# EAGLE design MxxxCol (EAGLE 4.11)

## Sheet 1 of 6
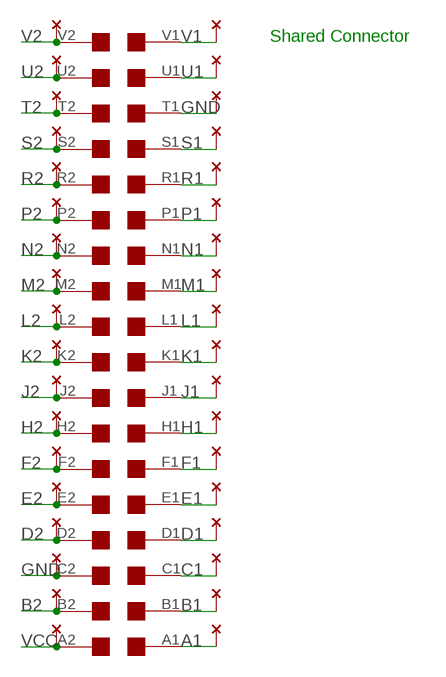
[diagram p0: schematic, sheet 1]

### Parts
U$1  EDGE-2  [EDGE-CON2]
U$4  THRU-HOLE2  [THRU-HOLEB]

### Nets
A1: U$1.A1 U$4.A2 ; also sheet 2,3,4,5,6
B1: U$1.B1 U$4.B2 ; also sheet 2,3,4,5,6
B2: U$1.B2 U$4.B1
C1: U$1.C1 U$4.C2 ; also sheet 2,3,4,5,6
D1: U$1.D1 U$4.D2 ; also sheet 2,3,4,5,6
D2: U$1.D2 U$4.D1 ; also sheet 2,3,4,5,6
E1: U$1.E1 U$4.E2 ; also sheet 2,3,4,5
E2: U$1.E2 U$4.E1 ; also sheet 2,3,4,5,6
F1: U$1.F1 U$4.F2 ; also sheet 2,3,4,5,6
F2: U$1.F2 U$4.F1 ; also sheet 2,3,4,5,6
GND [Power]: U$1.C2 U$1.T1 U$4.C1 U$4.T2 ; also sheet 2,3,4,5,6
H1: U$1.H1 U$4.H2 ; also sheet 2,3,4,5,6
H2: U$1.H2 U$4.H1 ; also sheet 2,3,4,5,6
J1: U$1.J1 U$4.J2 ; also sheet 2,3,4,5,6
J2: U$1.J2 U$4.J1 ; also sheet 2,3,4,5,6
K1: U$1.K1 U$4.K2 ; also sheet 2,3,4,5,6
K2: U$1.K2 U$4.K1 ; also sheet 2,3,4,5,6
L1: U$1.L1 U$4.L2 ; also sheet 2,3,4,5
L2: U$1.L2 U$4.L1 ; also sheet 2,3,4,5,6
M1: U$1.M1 U$4.M2 ; also sheet 2,3,4,5,6
M2: U$1.M2 U$4.M1 ; also sheet 2,3,4,5,6
N1: U$1.N1 U$4.N2 ; also sheet 2,3,4,5,6
N2: U$1.N2 U$4.N1 ; also sheet 2,3,4,5,6
P1: U$1.P1 U$4.P2 ; also sheet 2,3,4,5,6
P2: U$1.P2 U$4.P1 ; also sheet 2,3,4,5,6
R1: U$1.R1 U$4.R2 ; also sheet 2,3,4,5,6
R2: U$1.R2 U$4.R1 ; also sheet 2,3,4,5,6
S1: U$1.S1 U$4.S2 ; also sheet 2,3,4,5
S2: U$1.S2 U$4.S1 ; also sheet 2,3,4,5,6
T2: U$1.T2 U$4.T1 ; also sheet 2,3,4,5,6
U1: U$1.U1 U$4.U2 ; also sheet 2,3,4
U2: U$1.U2 U$4.U1 ; also sheet 2,3,4,5,6
V1: U$1.V1 U$4.V2 ; also sheet 2,3,4
V2: U$1.V2 U$4.V1 ; also sheet 2,3,4,5,6
VCC [Power]: U$1.A2 U$4.A1 ; also sheet 2,3,4,5,6

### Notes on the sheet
- Shared Connector

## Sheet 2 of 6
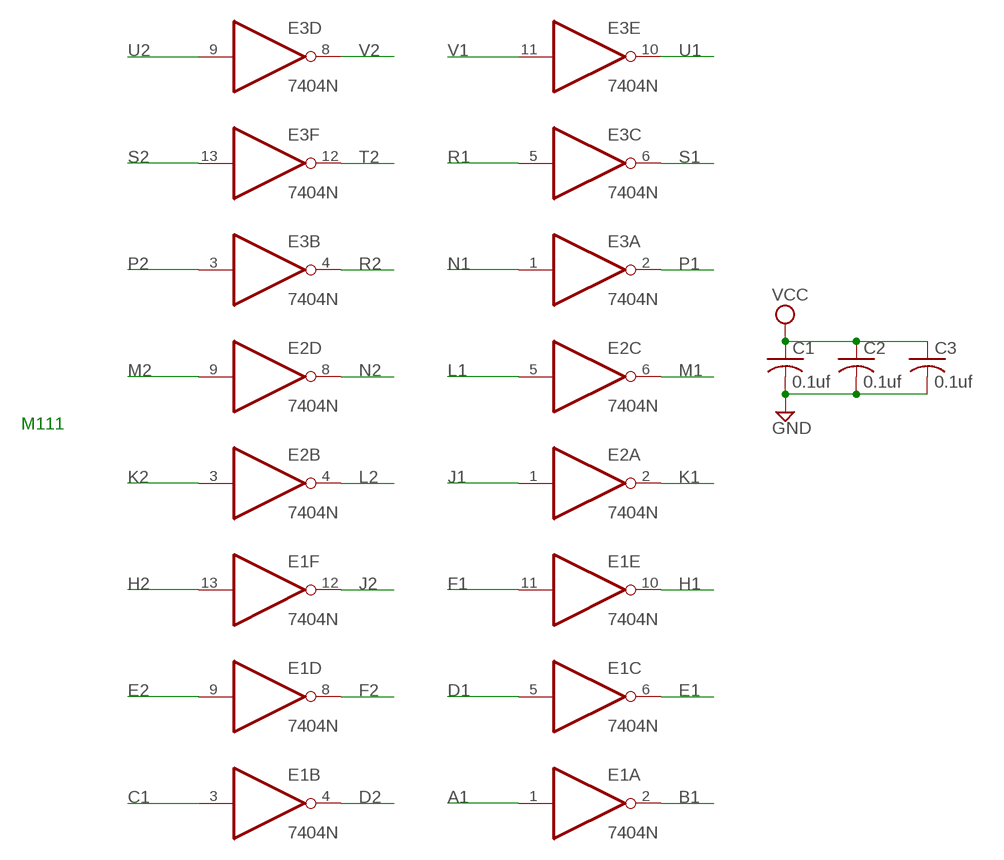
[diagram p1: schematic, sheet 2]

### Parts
C1  0.1uf  C-US050-025X075  [C050-025X075]
C2  0.1uf  C-US050-025X075  [C050-025X075]
C3  0.1uf  C-US050-025X075  [C050-025X075]
E1  7404N  [DIL14]
E2  7404N  [DIL14]
E3  7404N  [DIL14]

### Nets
A1: E1.1(A:I) ; also sheet 1,3,4,5,6
B1: E1.2(A:O) ; also sheet 1,3,4,5,6
C1: E1.3(B:I) ; also sheet 1,3,4,5,6
D1: E1.5(C:I) ; also sheet 1,3,4,5,6
D2: E1.4(B:O) ; also sheet 1,3,4,5,6
E1: E1.6(C:O) ; also sheet 1,3,4,5
E2: E1.9(D:I) ; also sheet 1,3,4,5,6
F1: E1.11(E:I) ; also sheet 1,3,4,5,6
F2: E1.8(D:O) ; also sheet 1,3,4,5,6
GND [Power]: C1.2 C2.2 C3.2 ; also sheet 1,3,4,5,6
H1: E1.10(E:O) ; also sheet 1,3,4,5,6
H2: E1.13(F:I) ; also sheet 1,3,4,5,6
J1: E2.1(A:I) ; also sheet 1,3,4,5,6
J2: E1.12(F:O) ; also sheet 1,3,4,5,6
K1: E2.2(A:O) ; also sheet 1,3,4,5,6
K2: E2.3(B:I) ; also sheet 1,3,4,5,6
L1: E2.5(C:I) ; also sheet 1,3,4,5
L2: E2.4(B:O) ; also sheet 1,3,4,5,6
M1: E2.6(C:O) ; also sheet 1,3,4,5,6
M2: E2.9(D:I) ; also sheet 1,3,4,5,6
N1: E3.1(A:I) ; also sheet 1,3,4,5,6
N2: E2.8(D:O) ; also sheet 1,3,4,5,6
P1: E3.2(A:O) ; also sheet 1,3,4,5,6
P2: E3.3(B:I) ; also sheet 1,3,4,5,6
R1: E3.5(C:I) ; also sheet 1,3,4,5,6
R2: E3.4(B:O) ; also sheet 1,3,4,5,6
S1: E3.6(C:O) ; also sheet 1,3,4,5
S2: E3.13(F:I) ; also sheet 1,3,4,5,6
T2: E3.12(F:O) ; also sheet 1,3,4,5,6
U1: E3.10(E:O) ; also sheet 1,3,4
U2: E3.9(D:I) ; also sheet 1,3,4,5,6
V1: E3.11(E:I) ; also sheet 1,3,4
V2: E3.8(D:O) ; also sheet 1,3,4,5,6
VCC [Power]: C1.1 C2.1 C3.1 ; also sheet 1,3,4,5,6
Unconnected: E2.10(E:O) E2.11(E:I) E2.12(F:O) E2.13(F:I)

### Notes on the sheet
- M111

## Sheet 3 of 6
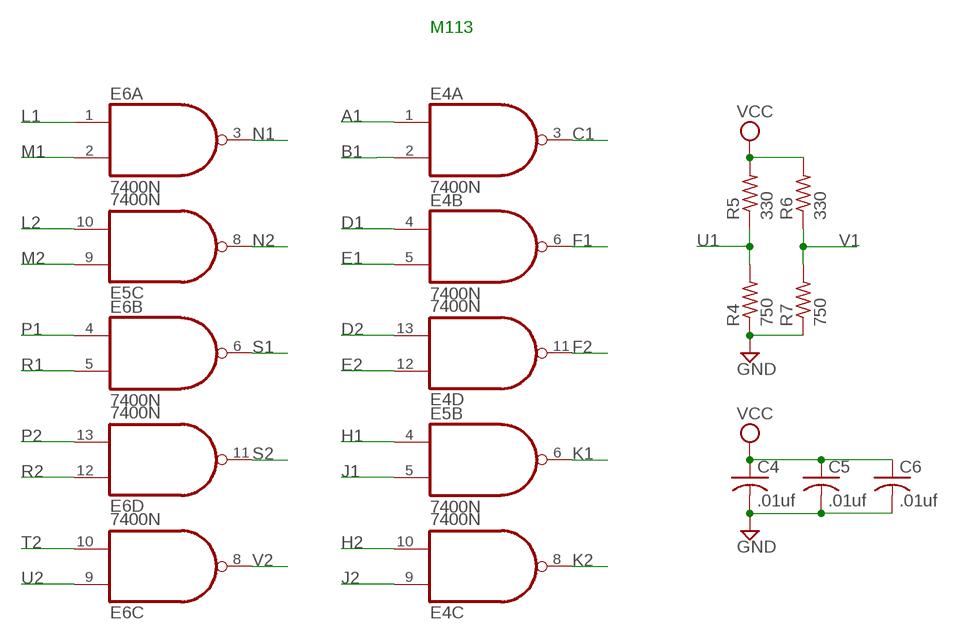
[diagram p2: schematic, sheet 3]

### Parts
C4  .01uf  C-US050-025X075  [C050-025X075]
C5  .01uf  C-US050-025X075  [C050-025X075]
C6  .01uf  C-US050-025X075  [C050-025X075]
E4  7400N  [DIL14]
E5  7400N  [DIL14]
E6  7400N  [DIL14]
R4  750  R-US_0207/10  [0207/10]
R5  330  R-US_0207/10  [0207/10]
R6  330  R-US_0207/10  [0207/10]
R7  750  R-US_0207/10  [0207/10]

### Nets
A1: E4.1(A:I0) ; also sheet 1,2,4,5,6
B1: E4.2(A:I1) ; also sheet 1,2,4,5,6
C1: E4.3(A:O) ; also sheet 1,2,4,5,6
D1: E4.4(B:I0) ; also sheet 1,2,4,5,6
D2: E4.13(D:I1) ; also sheet 1,2,4,5,6
E1: E4.5(B:I1) ; also sheet 1,2,4,5
E2: E4.12(D:I0) ; also sheet 1,2,4,5,6
F1: E4.6(B:O) ; also sheet 1,2,4,5,6
F2: E4.11(D:O) ; also sheet 1,2,4,5,6
GND [Power]: C4.2 C5.2 C6.2 R4.1 R7.1 ; also sheet 1,2,4,5,6
H1: E5.4(B:I0) ; also sheet 1,2,4,5,6
H2: E4.10(C:I1) ; also sheet 1,2,4,5,6
J1: E5.5(B:I1) ; also sheet 1,2,4,5,6
J2: E4.9(C:I0) ; also sheet 1,2,4,5,6
K1: E5.6(B:O) ; also sheet 1,2,4,5,6
K2: E4.8(C:O) ; also sheet 1,2,4,5,6
L1: E6.1(A:I0) ; also sheet 1,2,4,5
L2: E5.10(C:I1) ; also sheet 1,2,4,5,6
M1: E6.2(A:I1) ; also sheet 1,2,4,5,6
M2: E5.9(C:I0) ; also sheet 1,2,4,5,6
N1: E6.3(A:O) ; also sheet 1,2,4,5,6
N2: E5.8(C:O) ; also sheet 1,2,4,5,6
P1: E6.4(B:I0) ; also sheet 1,2,4,5,6
P2: E6.13(D:I1) ; also sheet 1,2,4,5,6
R1: E6.5(B:I1) ; also sheet 1,2,4,5,6
R2: E6.12(D:I0) ; also sheet 1,2,4,5,6
S1: E6.6(B:O) ; also sheet 1,2,4,5
S2: E6.11(D:O) ; also sheet 1,2,4,5,6
T2: E6.10(C:I1) ; also sheet 1,2,4,5,6
U1: R4.2 R5.1 ; also sheet 1,2,4
U2: E6.9(C:I0) ; also sheet 1,2,4,5,6
V1: R6.1 R7.2 ; also sheet 1,2,4
V2: E6.8(C:O) ; also sheet 1,2,4,5,6
VCC [Power]: C4.1 C5.1 C6.1 R5.2 R6.2 ; also sheet 1,2,4,5,6
Unconnected: E5.1(A:I0) E5.2(A:I1) E5.3(A:O) E5.11(D:O) E5.12(D:I0) E5.13(D:I1)

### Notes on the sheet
- M113

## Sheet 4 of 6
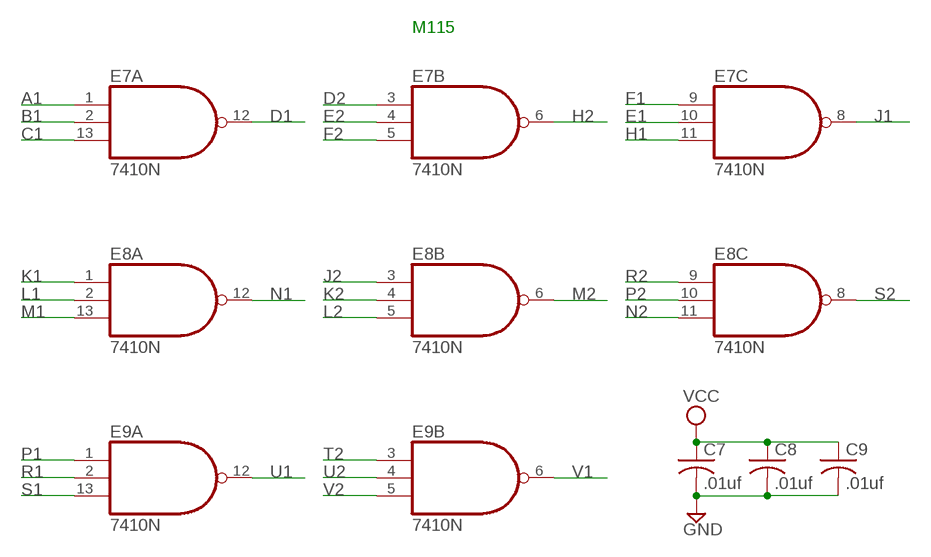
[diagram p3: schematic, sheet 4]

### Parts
C7  .01uf  C-US050-025X075  [C050-025X075]
C8  .01uf  C-US050-025X075  [C050-025X075]
C9  .01uf  C-US050-025X075  [C050-025X075]
E7  7410N  [DIL14]
E8  7410N  [DIL14]
E9  7410N  [DIL14]

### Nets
A1: E7.1(A:I0) ; also sheet 1,2,3,5,6
B1: E7.2(A:I1) ; also sheet 1,2,3,5,6
C1: E7.13(A:I2) ; also sheet 1,2,3,5,6
D1: E7.12(A:O) ; also sheet 1,2,3,5,6
D2: E7.3(B:I0) ; also sheet 1,2,3,5,6
E1: E7.10(C:I1) ; also sheet 1,2,3,5
E2: E7.4(B:I1) ; also sheet 1,2,3,5,6
F1: E7.9(C:I0) ; also sheet 1,2,3,5,6
F2: E7.5(B:I2) ; also sheet 1,2,3,5,6
GND [Power]: C7.2 C8.2 C9.2 ; also sheet 1,2,3,5,6
H1: E7.11(C:I2) ; also sheet 1,2,3,5,6
H2: E7.6(B:O) ; also sheet 1,2,3,5,6
J1: E7.8(C:O) ; also sheet 1,2,3,5,6
J2: E8.3(B:I0) ; also sheet 1,2,3,5,6
K1: E8.1(A:I0) ; also sheet 1,2,3,5,6
K2: E8.4(B:I1) ; also sheet 1,2,3,5,6
L1: E8.2(A:I1) ; also sheet 1,2,3,5
L2: E8.5(B:I2) ; also sheet 1,2,3,5,6
M1: E8.13(A:I2) ; also sheet 1,2,3,5,6
M2: E8.6(B:O) ; also sheet 1,2,3,5,6
N1: E8.12(A:O) ; also sheet 1,2,3,5,6
N2: E8.11(C:I2) ; also sheet 1,2,3,5,6
P1: E9.1(A:I0) ; also sheet 1,2,3,5,6
P2: E8.10(C:I1) ; also sheet 1,2,3,5,6
R1: E9.2(A:I1) ; also sheet 1,2,3,5,6
R2: E8.9(C:I0) ; also sheet 1,2,3,5,6
S1: E9.13(A:I2) ; also sheet 1,2,3,5
S2: E8.8(C:O) ; also sheet 1,2,3,5,6
T2: E9.3(B:I0) ; also sheet 1,2,3,5,6
U1: E9.12(A:O) ; also sheet 1,2,3
U2: E9.4(B:I1) ; also sheet 1,2,3,5,6
V1: E9.6(B:O) ; also sheet 1,2,3
V2: E9.5(B:I2) ; also sheet 1,2,3,5,6
VCC [Power]: C7.1 C8.1 C9.1 ; also sheet 1,2,3,5,6
Unconnected: E9.8(C:O) E9.9(C:I0) E9.10(C:I1) E9.11(C:I2)

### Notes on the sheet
- M115

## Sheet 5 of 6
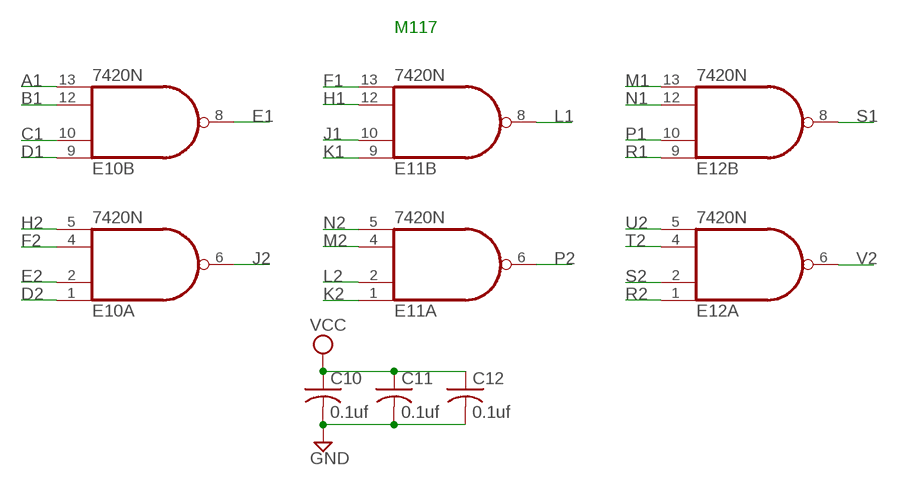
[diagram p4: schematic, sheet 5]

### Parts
C10  0.1uf  C-US050-025X075  [C050-025X075]
C11  0.1uf  C-US050-025X075  [C050-025X075]
C12  0.1uf  C-US050-025X075  [C050-025X075]
E10  7420N  74S20N  [DIL14]
E11  7420N  74S20N  [DIL14]
E12  7420N  74S20N  [DIL14]

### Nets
A1: E10.13(B:I3) ; also sheet 1,2,3,4,6
B1: E10.12(B:I2) ; also sheet 1,2,3,4,6
C1: E10.10(B:I1) ; also sheet 1,2,3,4,6
D1: E10.9(B:I0) ; also sheet 1,2,3,4,6
D2: E10.1(A:I0) ; also sheet 1,2,3,4,6
E1: E10.8(B:O) ; also sheet 1,2,3,4
E2: E10.2(A:I1) ; also sheet 1,2,3,4,6
F1: E11.13(B:I3) ; also sheet 1,2,3,4,6
F2: E10.4(A:I2) ; also sheet 1,2,3,4,6
GND [Power]: C10.2 C11.2 C12.2 ; also sheet 1,2,3,4,6
H1: E11.12(B:I2) ; also sheet 1,2,3,4,6
H2: E10.5(A:I3) ; also sheet 1,2,3,4,6
J1: E11.10(B:I1) ; also sheet 1,2,3,4,6
J2: E10.6(A:O) ; also sheet 1,2,3,4,6
K1: E11.9(B:I0) ; also sheet 1,2,3,4,6
K2: E11.1(A:I0) ; also sheet 1,2,3,4,6
L1: E11.8(B:O) ; also sheet 1,2,3,4
L2: E11.2(A:I1) ; also sheet 1,2,3,4,6
M1: E12.13(B:I3) ; also sheet 1,2,3,4,6
M2: E11.4(A:I2) ; also sheet 1,2,3,4,6
N1: E12.12(B:I2) ; also sheet 1,2,3,4,6
N2: E11.5(A:I3) ; also sheet 1,2,3,4,6
P1: E12.10(B:I1) ; also sheet 1,2,3,4,6
P2: E11.6(A:O) ; also sheet 1,2,3,4,6
R1: E12.9(B:I0) ; also sheet 1,2,3,4,6
R2: E12.1(A:I0) ; also sheet 1,2,3,4,6
S1: E12.8(B:O) ; also sheet 1,2,3,4
S2: E12.2(A:I1) ; also sheet 1,2,3,4,6
T2: E12.4(A:I2) ; also sheet 1,2,3,4,6
U2: E12.5(A:I3) ; also sheet 1,2,3,4,6
V2: E12.6(A:O) ; also sheet 1,2,3,4,6
VCC [Power]: C10.1 C11.1 C12.1 ; also sheet 1,2,3,4,6

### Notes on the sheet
- M117

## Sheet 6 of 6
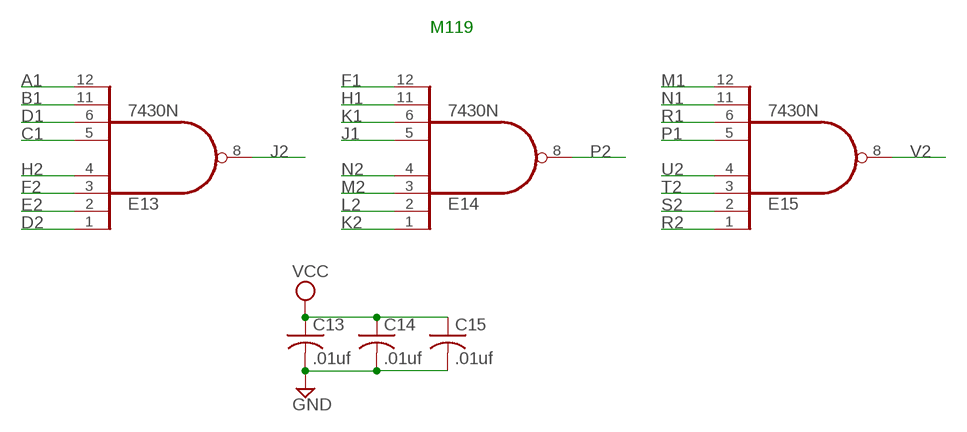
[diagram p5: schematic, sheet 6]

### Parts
C13  .01uf  C-US050-025X075  [C050-025X075]
C14  .01uf  C-US050-025X075  [C050-025X075]
C15  .01uf  C-US050-025X075  [C050-025X075]
E13  7430N  [DIL14]
E14  7430N  [DIL14]
E15  7430N  [DIL14]

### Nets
A1: E13.12(I7) ; also sheet 1,2,3,4,5
B1: E13.11(I6) ; also sheet 1,2,3,4,5
C1: E13.5(I4) ; also sheet 1,2,3,4,5
D1: E13.6(I5) ; also sheet 1,2,3,4,5
D2: E13.1(I0) ; also sheet 1,2,3,4,5
E2: E13.2(I1) ; also sheet 1,2,3,4,5
F1: E14.12(I7) ; also sheet 1,2,3,4,5
F2: E13.3(I2) ; also sheet 1,2,3,4,5
GND [Power]: C13.2 C14.2 C15.2 ; also sheet 1,2,3,4,5
H1: E14.11(I6) ; also sheet 1,2,3,4,5
H2: E13.4(I3) ; also sheet 1,2,3,4,5
J1: E14.5(I4) ; also sheet 1,2,3,4,5
J2: E13.8(O) ; also sheet 1,2,3,4,5
K1: E14.6(I5) ; also sheet 1,2,3,4,5
K2: E14.1(I0) ; also sheet 1,2,3,4,5
L2: E14.2(I1) ; also sheet 1,2,3,4,5
M1: E15.12(I7) ; also sheet 1,2,3,4,5
M2: E14.3(I2) ; also sheet 1,2,3,4,5
N1: E15.11(I6) ; also sheet 1,2,3,4,5
N2: E14.4(I3) ; also sheet 1,2,3,4,5
P1: E15.5(I4) ; also sheet 1,2,3,4,5
P2: E14.8(O) ; also sheet 1,2,3,4,5
R1: E15.6(I5) ; also sheet 1,2,3,4,5
R2: E15.1(I0) ; also sheet 1,2,3,4,5
S2: E15.2(I1) ; also sheet 1,2,3,4,5
T2: E15.3(I2) ; also sheet 1,2,3,4,5
U2: E15.4(I3) ; also sheet 1,2,3,4,5
V2: E15.8(O) ; also sheet 1,2,3,4,5
VCC [Power]: C13.1 C14.1 C15.1 ; also sheet 1,2,3,4,5

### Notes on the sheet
- M119

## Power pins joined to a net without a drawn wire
GND: E1.7(P:GND) E2.7(P:GND) E3.7(P:GND) E4.7(P:GND) E5.7(P:GND) E6.7(P:GND) E7.7(P:GND) E8.7(P:GND) E9.7(P:GND) E10.7(P:GND) E11.7(P:GND) E12.7(P:GND) E13.7(GND) E14.7(GND) E15.7(GND)
VCC: E1.14(P:VCC) E2.14(P:VCC) E3.14(P:VCC) E4.14(P:VCC) E5.14(P:VCC) E6.14(P:VCC) E7.14(P:VCC) E8.14(P:VCC) E9.14(P:VCC) E10.14(P:VCC) E11.14(P:VCC) E12.14(P:VCC) E13.14(VCC) E14.14(VCC) E15.14(VCC)

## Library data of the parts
C1-C15 = rcl:C-US: CAPACITOR, American symbol
E1-E3 = 74xx-us:74*04: Hex INVERTER
E4-E6 = 74xx-us:74*00: Quad 2-input NAND gate
E7-E9 = 74xx-us:74*10: Triple 3-input NAND gate
E10-E12 = 74xx-us:74*20: Dual 4-input NAND gate
E13-E15 = 74xx-us:74*30: 8-input NAND gate
R4-R7 = rcl:R-US_: RESISTOR, American symbol
U$1 = dec-con:EDGE-2: Double-Sided DEC edge connector.
U$4 = dec-con:THRU-HOLE2: Thru-Hole addition to double-sided edge connector.

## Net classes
1 Power: width 0.381 mm

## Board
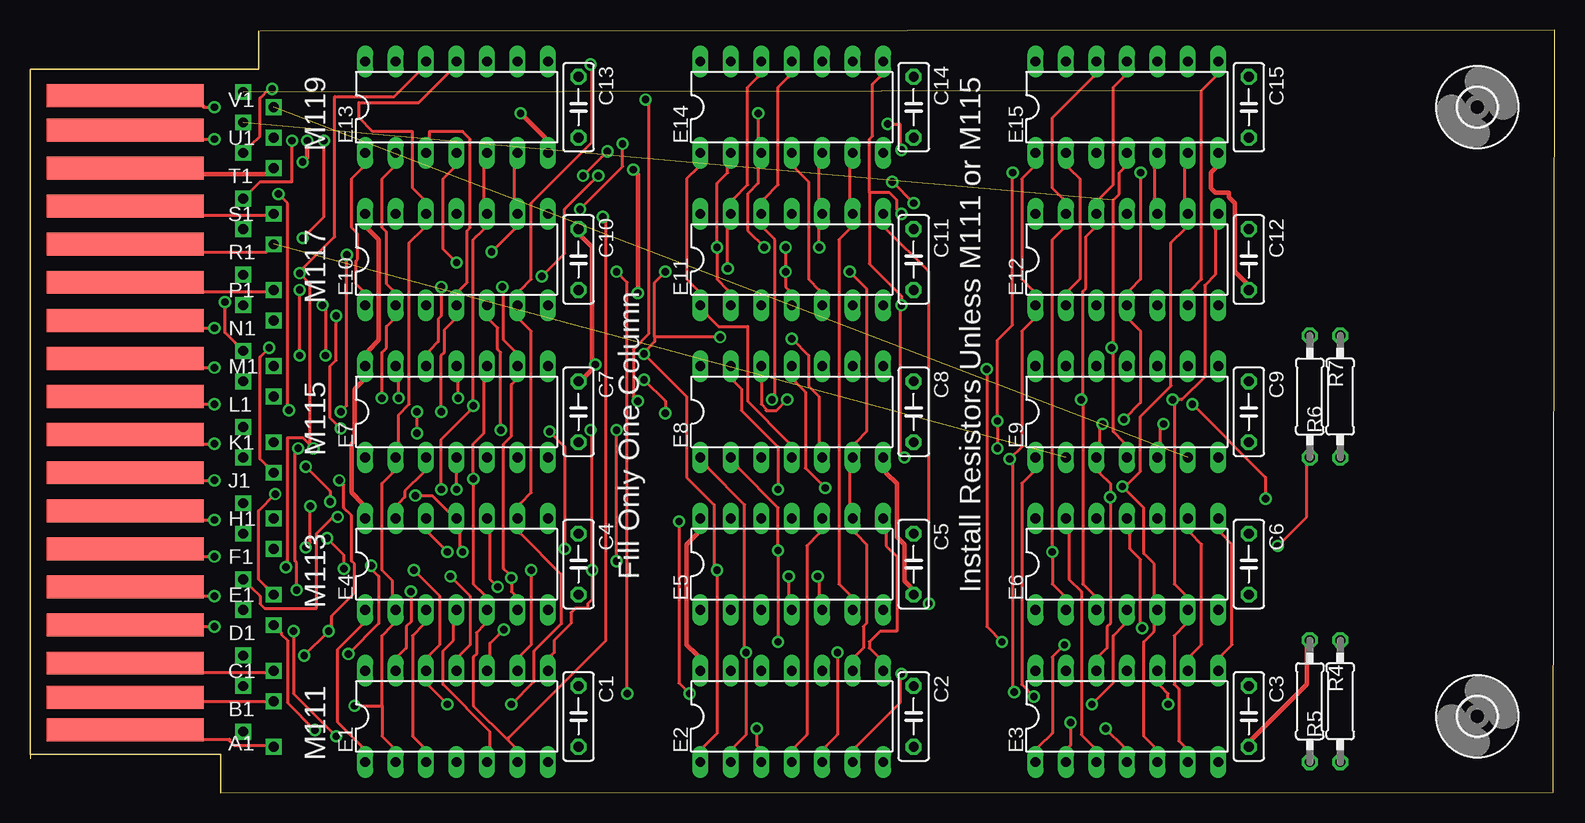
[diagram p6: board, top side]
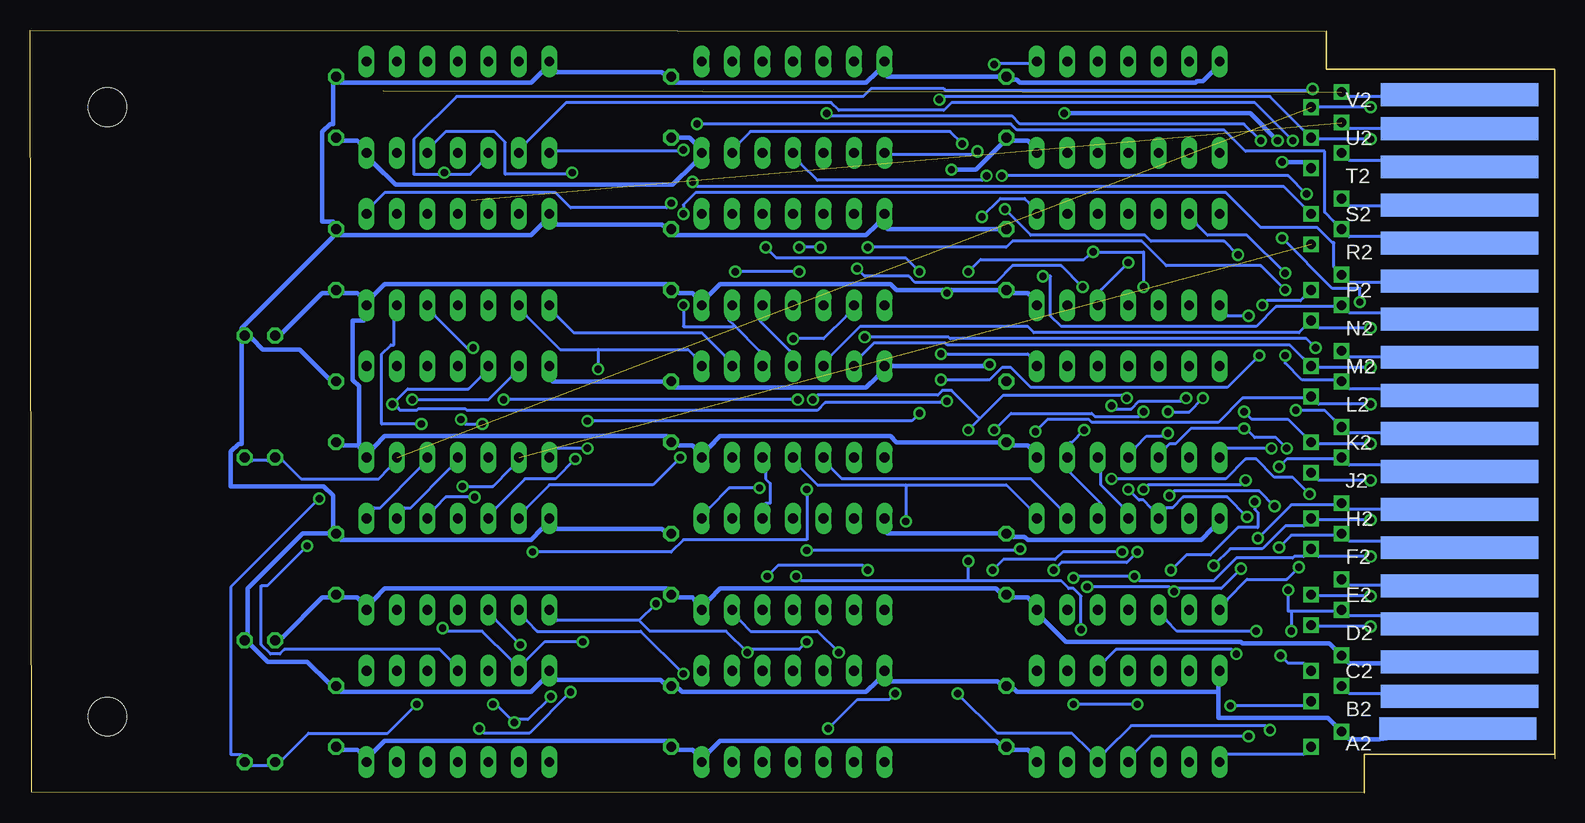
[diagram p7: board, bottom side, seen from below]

Size 127.11 x 63.59 mm. Coordinates in mm from the lower left corner, seen from the top.
Outline: 15.88,0 126.98,0.04 127.11,63.59 19.18,63.5
Outline: 0.01,59.65 0.01,2.83
Copper layers (1*16): Top 0.035mm / dielectric 1.5mm / Bottom 0.035mm
Design rules "10mils": minimum track width 10mil, minimum drill 24mil, track to track 10mil, track to pad 10mil, pad to pad 10mil, via to via 10mil, smd to smd 10mil, copper to edge 40mil, drill to drill 10mil, minimum pad ring 10mil, minimum via ring 8mil, stop-mask expansion 0mil, vias tented up to drill 0mil, thermal gap 10mil

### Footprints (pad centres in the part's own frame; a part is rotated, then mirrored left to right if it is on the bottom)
C050-025X075 = drill 0.813 octagon: 1 -2.54,0; 2 2.54,0
DIL14 = drill 0.813 long: 1 -7.62,-3.81; 2 -5.08,-3.81; 3 -2.54,-3.81; 4 0,-3.81; 5 2.54,-3.81; 6 5.08,-3.81; 7 7.62,-3.81; 8 7.62,3.81; 9 5.08,3.81; 10 2.54,3.81; 11 0,3.81; 12 -2.54,3.81; 13 -5.08,3.81; 14 -7.62,3.81
0207/10 = drill 0.813 octagon: 1 -5.08,0; 2 5.08,0
EDGE-CON2 = smd 13.106 x 1.905: A1 7.938,5.239; B1 7.938,7.938; C1 7.938,10.795; D1 7.938,13.97; E1 7.938,17.145; F1 7.938,20.32; H1 7.938,23.495; J1 7.938,26.67; K1 7.938,29.845; L1 7.938,33.02; M1 7.938,36.195; N1 7.938,39.37; P1 7.938,42.545; R1 7.938,45.72; S1 7.938,48.895; T1 7.938,52.07; U1 7.938,55.245; V1 7.938,58.102 | smd 13.106 x 1.905 bottom: A2 8.096,5.34; B2 7.938,8.039; C2 7.938,10.897; D2 7.938,14.072; E2 7.938,17.247; F2 7.938,20.422; H2 7.938,23.597; J2 7.938,26.772; K2 7.938,29.947; L2 7.938,33.122; M2 7.938,36.297; N2 7.938,39.472; P2 7.938,42.647; R2 7.938,45.822; S2 7.938,48.997; T2 7.938,52.172; U2 7.938,55.347; V2 7.938,58.204
3,2 = hole 3.2: 0,0
THRU-HOLEB = drill 0.813 square: A1 17.78,5.08; A2 20.32,3.81; B1 17.78,8.89; B2 20.32,7.62; C1 17.78,11.43; C2 20.32,10.16; D1 17.78,15.24; D2 20.32,13.97; E1 17.78,17.78; E2 20.32,16.51; F1 17.78,21.59; F2 20.32,20.32; H1 17.78,24.13; H2 20.32,22.86; J1 17.78,27.94; J2 20.32,26.67; K1 17.78,30.48; K2 20.32,29.21; L1 17.78,34.29; L2 20.32,33.02; M1 17.78,36.83; M2 20.32,35.56; N1 17.78,40.64; N2 20.32,39.37; P1 17.78,43.18; P2 20.32,41.91; R1 17.78,46.99; R2 20.32,45.72; S1 17.78,49.53; S2 20.32,48.26; T1 17.78,53.34; T2 20.32,52.07; U1 17.78,55.88; U2 20.32,54.61; V1 17.78,58.42; V2 20.32,57.15

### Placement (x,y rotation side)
C1  45.72,6.35 270 top
C2  73.66,6.35 270 top
C3  101.6,6.35 270 top
C4  45.72,19.05 270 top
C5  73.66,19.05 270 top
C6  101.6,19.05 270 top
C7  45.72,31.75 270 top
C8  73.66,31.75 270 top
C9  101.6,31.75 270 top
C10  45.72,44.45 270 top
C11  73.66,44.45 270 top
C12  101.6,44.45 270 top
C13  45.72,57.15 270 top
C14  73.66,57.15 270 top
C15  101.6,57.15 270 top
E1  35.56,6.35 0 top
E2  63.5,6.35 0 top
E3  91.44,6.35 0 top
E4  35.56,19.05 0 top
E5  63.5,19.05 0 top
E6  91.44,19.05 0 top
E7  35.56,31.75 0 top
E8  63.5,31.75 0 top
E9  91.44,31.75 0 top
E10  35.56,44.45 0 top
E11  63.5,44.45 0 top
E12  91.44,44.45 0 top
E13  35.56,57.15 0 top
E14  63.5,57.15 0 top
E15  91.44,57.15 0 top
R4  106.68,7.62 270 top
R5  109.22,7.62 90 top
R6  109.22,33.02 90 top
R7  106.68,33.02 270 top
U$1  0,0 0 top
U$2  [3,2]  120.65,6.35 0 top
U$3  [3,2]  120.65,57.15 0 top
U$4  0,0 0 top

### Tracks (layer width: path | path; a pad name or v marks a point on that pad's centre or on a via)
A1  (via drill 0.61)
  Top 0.254: E4.1 27.69,13.97 25.65,11.94 25.65,5.84 27.69,3.81 E1.1 | v21.34,18.8 21.46,18.92 21.46,29.59 22.73,29.59 v23.62,28.7 23.37,29.08 23.37,42.42 v22.48,43.31 22.73,43.69 25.4,46.35 25.4,58.04 30.35,58.04 32.38,60.07 E13.12 | U$1.A1 14.48,4.45 16.64,4.45 16.64,4.32 17.02,3.94 19.68,3.94 U$4.A2
  Bottom 0.254: E1.1 27.3,3.17 20.95,3.17 U$4.A2 | v23.62,28.7 27.3,28.7 E7.1 | v21.34,18.8 22.35,17.78 25.65,17.78 27.3,16.13 E4.1 | v22.48,43.31 25.65,46.48 28.96,46.48 29.84,47.37 E10.13
B1  (via drill 0.61)
  Top 0.254: U$4.B2 19.68,7.62 14.48,7.62 U$1.B1 | 29.34,7.24 29.34,13.08 30.23,13.97 E4.2 30.23,16.51 30.23,17.65 29.34,18.54 29.34,25.78 30.23,26.67 E7.2 30.73,29.21 30.73,31.5 31.62,32.38 31.62,45.85 32.77,46.99 E10.12 32.77,49.53 31.88,50.42 31.88,55.12 28.57,55.12 27.43,56.26 27.43,57.53 32.38,57.53 34.92,60.07 E13.11 | 29.34,7.24 29.34,4.7 30.23,3.81 E1.2 | v27.05,7.24 29.34,7.24
  Bottom 0.254: v27.05,7.24 20.95,7.24 U$4.B2
B2
  Bottom 0.254: U$4.B1 17.14,8.26 14.48,8.26 U$1.B2
C1  (via drill 0.61)
  Top 0.254: v30.73,32.89 30.73,34.29 E7.13 | E13.5 37.85,52.07 37.85,49.53 E10.10 37.85,46.99 36.96,46.1 v36.96,32.26 36.7,31.88 34.29,29.46 v34.29,25.27 | E1.3 32.77,3.81 31.88,4.7 31.88,13.08 32.77,13.97 E4.3 | U$4.C2 19.68,10.03 14.48,10.03 U$1.C1 | v22.86,11.43 v24.89,13.46 25.15,13.84 25.15,14.73 27.05,16.64 27.05,19.05 26.8,19.3 26.8,23.11 26.16,23.75 26.16,25.65 v25.78,26.04
  Bottom 0.254: v30.73,32.89 30.99,32.64 34.67,32.64 35.31,32 36.7,32 v36.96,32.26 | v24.89,13.46 31.5,13.46 32.38,14.35 E4.3 | v22.86,11.43 22.23,10.79 20.95,10.79 U$4.C2 | v34.29,25.27 33.91,25.65 26.16,25.65 v25.78,26.04
D1  (via drill 0.61)
  Top 0.254: v34.29,42.16 34.29,39.75 34.04,39.5 34.04,37.59 33.27,36.83 E7.12 | v38.48,45.09 40.39,46.99 E10.9 40.39,49.53 40.39,52.07 E13.6 | E1.5 38.35,3.81 38.35,5.08 34.42,9.02 34.42,11.81 35.31,12.7 35.31,13.97 E4.4 | v15.37,13.84 14.48,13.84 U$1.D1 | v23.75,5.21 21.46,7.49 21.46,12.7 20.95,13.21 20.95,13.34 U$4.D2 | v48.9,43.43 49.78,42.55 v49.78,8.26
  Bottom 0.254: v34.29,42.16 34.29,45.09 v38.48,45.09 38.86,44.83 39.24,44.45 47.88,44.45 v48.9,43.43 | v15.37,13.84 19.68,13.84 U$4.D2 | v23.75,5.21 24.13,5.59 35.31,5.59 37.47,3.43 E1.5 38.73,3.43 40.26,4.95 46.48,4.95 v49.78,8.26
D2  (via drill 0.61)
  Top 0.254: E4.13 30.73,24.13 31.24,24.64 31.24,25.15 32.77,26.67 E7.3 | E10.1 27.69,41.91 27.18,42.42 27.18,44.32 27.3,44.45 27.3,46.61 26.8,47.12 26.8,51.18 27.69,52.07 E13.1 | v25.91,30.35 25.02,31.24 25.02,35.56 25.53,36.07 v25.53,39.75 | v25.53,4.7 21.97,8.26 v21.97,13.46 | v22.35,28.7 22.1,28.45 22.1,19.3 22.23,19.18 v22.23,16.89
  Bottom 0.254: v25.53,39.75 27.3,39.75 E10.1 | E7.3 32.38,28.83 32.13,29.08 31.62,29.08 30.35,30.35 v25.91,30.35 25.53,30.1 25.02,29.59 23.24,29.59 v22.35,28.7 | U$1.D2 14.48,14.73 17.14,14.73 U$4.D1 18.41,15.11 21.97,15.11 | v25.53,4.7 33.66,4.7 34.92,3.43 E1.4 | 21.97,15.11 v21.97,13.46 | v22.23,16.89 22.23,15.11 21.97,15.11
E1  (via drill 0.61)
  Top 0.254: v15.37,16.38 14.48,16.38 U$1.E1 | 39.81,4.38 40.39,3.81 E1.6 | 39.81,4.38 36.96,7.24 36.96,11.3 37.21,11.56 37.21,13.34 37.85,13.97 E4.5 37.85,16.51 36.96,17.4 v36.96,26.16 36.96,29.08 37.85,29.97 37.85,34.29 E7.10 | v47.75,48.01 48.01,47.75 48.01,12.7 39.88,4.57 39.88,4.45 39.81,4.38 | v20.45,24.89 19.05,23.5 19.05,17.78 19.68,17.14 U$4.E2
  Bottom 0.254: v15.37,16.38 19.68,16.38 U$4.E2 | v47.75,48.01 46.23,49.53 44.2,49.53 43.81,49.15 E10.8 | v20.45,24.89 21.84,26.29 23.37,26.29 24.89,27.81 25.78,27.81 27.43,26.16 v36.96,26.16
E2  (via drill 0.61)
  Top 0.254: E13.2 30.23,52.07 29.34,51.18 29.34,47.12 29.72,46.74 29.72,42.42 30.23,41.91 E10.2 30.23,39.37 29.72,38.86 29.72,37.08 29.34,36.7 v29.34,32.89 | v35.56,25.27 35.56,26.67 E7.4 | v41.78,18.54 41.78,12.32 40.89,11.43 E1.9 | v34.8,20.07 33.27,21.59 E4.12 | v32.26,29.97 v32.26,31.75 | v25.65,22.99 25.27,22.99 23.88,21.59 23.88,15.37 19.56,15.37 19.18,15.75 19.18,16.38 18.41,17.14 U$4.E1
  Bottom 0.254: U$4.E1 17.14,17.27 14.48,17.27 U$1.E2 | v35.56,25.27 34.67,24.38 34.29,24.38 33.66,23.75 E4.12 32.38,23.75 31.88,23.75 30.99,24.64 27.3,24.64 v25.65,22.99 | v41.78,18.54 41.15,19.18 35.69,19.18 v34.8,20.07 | v29.34,32.89 30.48,31.75 v32.26,31.75 | v32.26,29.97 32.51,29.72 34.04,29.72 34.92,28.83 E7.4
F1  (via drill 0.61)
  Top 0.254: E14.12 60.71,59.69 59.82,58.8 59.82,50.67 58.67,49.53 E11.13 58.17,46.99 v58.17,43.69 | v15.37,19.68 14.48,19.68 U$1.F1 | v35.05,18.03 36.7,16.38 36.7,12.32 35.81,11.43 E1.11 | E4.6 40.39,16.51 40.13,16.76 v40.13,17.91 39.88,18.29 39.5,18.67 39.5,29.08 40.13,29.72 40.13,34.04 40.39,34.29 E7.9 40.39,36.83 39.5,37.72 39.5,42.04 v39.37,42.16
  Bottom 0.254: v15.37,19.68 19.68,19.68 U$4.F2 20.95,19.68 21.72,19.68 21.84,19.56 26.54,19.56 28.45,17.65 34.67,17.65 v35.05,18.03 35.43,18.03 40.01,18.03 v40.13,17.91 | v58.17,43.69 57.53,43.05 53.85,43.05 53.34,42.55 46.61,42.55 45.21,43.94 41.15,43.94 v39.37,42.16
F2  (via drill 0.61)
  Top 0.254: E13.3 33.27,54.61 33.27,55.12 36.07,55.12 36.7,54.48 36.7,47.12 36.45,46.86 36.45,42.55 35.81,41.91 E10.4 35.31,39.37 34.54,38.61 34.54,36.7 34.29,36.45 v34.29,31.75 | v36.07,20.07 35.81,20.32 35.81,21.59 E4.11 34.92,23.37 33.53,24.77 v32.13,24.77 | E1.8 43.43,11.43 43.69,11.68 43.69,12.7 45.09,14.1 45.09,14.99 45.47,15.37 46.48,15.37 46.48,15.75 46.86,16.13 v46.86,18.54 46.86,18.92 46.86,30.1 v46.74,30.23 | v22.99,20.45 23.37,20.83 v23.37,23.88
  Bottom 0.254: U$1.F2 14.48,20.95 17.14,20.95 U$4.F1 18.41,21.46 21.97,21.46 v22.99,20.45 | E4.11 36.07,23.88 37.85,25.65 37.85,26.67 E7.5 | v46.86,18.54 45.97,19.43 41.66,19.43 41.02,20.07 v36.07,20.07 | v34.29,31.75 34.67,31.37 38.35,31.37 38.61,31.62 45.34,31.62 v46.74,30.23 | v23.37,23.88 24.64,25.15 31.75,25.15 v32.13,24.77
GND  (via drill 0.61)
  Top 0.381: C3.2 101.85,4.45 106.43,9.02 106.43,12.06 R4.1 | E15.7 98.81,52.07 98.42,51.69 98.42,50.42 98.81,50.04 99.95,50.04 99.95,49.66 100.46,49.15 100.46,43.43 101.35,42.55 C12.2 | U$4.T2 19.68,51.56 14.48,51.56 U$1.T1 | v50.29,51.94 50.67,51.56 v50.67,41.66 | C5.2 73.41,17.14 72.9,17.65 72.9,20.7 72.26,21.34 72.26,25.78 71.37,26.67 E8.7 | v22.73,52.58 23.11,52.96 v23.11,54.36 | v40.89,56.64 42.93,54.61 E13.7
  Bottom 0.381: C3.2 100.97,3.56 99.82,3.56 99.69,3.43 E3.7 98.42,3.43 97.54,4.32 74.04,4.32 C2.2 73.03,3.56 71.88,3.56 71.75,3.43 E2.7 70.48,3.43 69.6,4.32 46.61,4.32 46.35,4.06 C1.2 45.09,3.56 43.94,3.56 43.81,3.43 E1.7 | U$1.C2 14.48,10.79 17.14,10.79 U$4.C1 18.41,12.06 18.8,12.45 26.04,12.45 26.16,12.57 40.77,12.57 42.55,14.35 E4.7 43.81,16.13 43.94,16.26 45.09,16.26 C4.2 46.35,16.76 46.61,17.02 69.6,17.02 70.48,16.13 E5.7 71.75,16.13 71.88,16.26 73.03,16.26 C5.2 74.04,17.02 97.54,17.02 98.42,16.13 E6.7 99.69,16.13 99.82,16.26 100.97,16.26 C6.2 102.23,16.26 102.74,16.26 106.05,12.95 R4.1 | C14.2 73.03,54.61 72.14,54.61 71.75,54.23 E14.7 71.75,52.45 73.53,50.67 96.65,50.67 98.42,52.45 E15.7 99.69,54.23 99.82,54.36 100.97,54.36 C15.2 | 99.82,28.96 99.69,28.83 E9.7 98.42,28.83 97.54,29.72 74.04,29.72 C8.2 73.03,28.96 71.88,28.96 71.75,28.83 E8.7 70.48,28.83 69.6,29.72 55.37,29.72 54.86,29.21 46.35,29.21 C7.2 45.09,28.96 43.94,28.96 43.81,28.83 E7.7 | 99.82,28.96 100.97,28.96 C9.2 | E12.7 99.69,41.53 99.82,41.66 100.97,41.66 C12.2 102.23,41.66 102.74,41.66 106.05,38.35 R7.1 | 99.82,28.96 99.69,29.08 99.69,33.91 100.2,34.42 100.2,39.37 99.31,39.37 E12.7 | E13.7 43.81,54.23 43.94,54.36 45.09,54.36 C13.2 46.1,54.1 48.26,51.94 v50.29,51.94 | E10.7 43.81,41.53 43.94,41.66 45.09,41.66 C10.2 46.35,41.91 50.67,41.91 | 50.67,41.91 54.86,41.91 55.37,42.42 69.6,42.42 70.48,41.53 E11.7 71.75,41.53 71.88,41.66 73.03,41.66 C11.2 74.04,42.42 97.54,42.42 98.42,41.53 E12.7 | v50.67,41.66 50.67,41.78 50.67,41.91 | v22.73,52.58 20.95,52.58 U$4.T2
  Bottom 0.381: v23.11,54.36 25.4,56.64 v40.89,56.64
H1  (via drill 0.61)
  Top 0.254: E14.11 63.25,59.69 62.36,58.8 62.36,50.67 61.21,49.53 E11.12 61.21,46.99 62.1,46.1 62.1,33.02 v61.85,32.77 | v15.37,22.73 14.48,22.73 U$1.H1 | v26.54,11.56 29.08,14.1 29.08,18.03 28.45,18.67 v28.45,18.92 | v63.25,18.03 63.25,16.51 E5.4 | v39.5,13.59 38.35,12.45 38.35,11.43 E1.10 | v35.69,32.89 35.69,34.29 E7.11 | v48.9,19.3 v48.9,30.23
  Bottom 0.254: v15.37,22.73 19.68,22.73 U$4.H2 20.95,22.23 22.48,22.23 24.38,20.32 27.05,20.32 v28.45,18.92 | v26.54,11.56 26.92,11.94 36.58,11.94 37.47,11.05 E1.10 | v63.25,18.03 62.87,17.65 48.9,17.65 | 48.9,17.65 41.15,17.65 40.51,17.02 40.13,17.02 39.5,16.38 v39.5,13.59 | v35.69,32.89 35.94,33.15 45.97,33.15 47.94,31.18 | v48.9,30.23 47.94,31.18 | 48.9,17.65 v48.9,19.3 | v61.85,32.77 61.47,33.15 51.44,33.15 51.05,33.53 50.29,33.53 48.01,31.24 47.94,31.18
H2  (via drill 0.61)
  Top 0.254: v35.56,44.2 34.42,45.34 34.42,51.18 35.31,52.07 E13.4 | v31.75,16.76 31.75,14.22 31.37,13.84 31.37,12.06 30.73,11.43 E1.13 | v38.99,17.14 38.35,17.78 38.35,21.59 E4.10 | v39.24,30.23 39.24,36.7 38.99,36.96 38.99,38.73 38.35,39.37 E10.5 | v24.77,21.21 26.16,19.81 v26.16,18.67
  Bottom 0.254: U$1.H2 14.48,23.62 17.14,23.62 U$4.H1 18.41,24 21.97,24 v24.77,21.21 | v35.56,44.2 37.85,41.91 E10.5 | v38.99,17.14 32.13,17.14 v31.75,16.76 31.37,17.02 27.81,17.02 v26.16,18.67 | E4.10 37.85,24.13 40.39,26.67 E7.6 40.39,29.21 40.26,29.21 v39.24,30.23
J1  (via drill 0.61)
  Top 0.254: v15.37,26.04 14.48,26.04 U$1.J1 | E14.5 65.79,52.07 65.79,49.53 E11.10 65.79,46.99 v65.79,45.47 | v65.66,18.03 65.79,17.91 65.79,16.51 E5.5 | E2.1 56.13,3.81 57.28,4.95 v57.28,18.54 57.02,18.92 57.02,24 54.74,26.29 54.74,33.02 v51.18,36.58 51.44,36.96 52.07,37.59 52.07,37.97 | v52.96,43.43 52.07,42.55 52.07,37.97 | v19.94,37.08 19.18,36.32 19.18,27.81 19.68,27.3 U$4.J2 | v57.53,37.97 52.07,37.97
  Bottom 0.254: v15.37,26.04 19.68,26.04 U$4.J2 | v57.28,18.54 57.66,18.92 64.77,18.92 v65.66,18.03 | v51.18,36.58 43.94,36.58 43.81,36.45 E7.8 | v65.79,45.47 64.9,44.58 54.1,44.58 v52.96,43.43 | v19.94,37.08 20.7,37.85 50.42,37.85 50.55,37.97 v57.53,37.97
J2  (via drill 0.61)
  Top 0.254: v34.8,7.37 33.27,8.89 E1.12 33.27,11.43 34.16,12.32 34.16,16.38 v32,18.54 | v40.13,7.37 42.04,9.27 42.04,11.81 44.32,14.1 44.32,18.16 40.89,21.59 E4.9 40.89,24.13 41.78,25.02 41.78,38.48 40.89,39.37 E10.6 40.89,41.91 41.78,42.8 41.78,49.15 46.86,54.23 46.86,60.58 v46.74,60.71 | v22.99,27.18 25.02,25.15 v25.02,24.26
  Bottom 0.254: U$1.J2 14.48,27.3 17.14,27.3 U$4.J1 18.41,27.81 22.35,27.81 v22.99,27.18 | v34.8,7.37 v40.13,7.37 | E8.3 60.33,27.05 59.44,26.16 43.69,26.16 41.27,23.75 E4.9 | v46.74,60.71 46.61,60.83 43.81,60.83 E13.8 | v25.02,24.26 25.02,23.62 24.77,23.37 24.77,22.1 26.42,22.1 28.7,19.81 30.73,19.81 v32,18.54
K1  (via drill 0.61)
  Top 0.254: v15.37,29.08 14.48,29.08 U$1.K1 | E14.6 68.33,52.07 68.33,49.53 E11.9 68.33,46.99 67.44,46.1 67.44,17.4 68.33,16.51 E5.6 | E2.2 58.67,3.81 59.69,4.83 v59.69,11.68 59.56,12.06 59.56,24 56.52,27.05 E8.1 | v25.91,31.75 26.42,32.26 v26.42,44.83 | v45.85,48.64 49.4,52.2 v49.4,54.1
  Bottom 0.254: v15.37,29.08 19.68,29.08 U$4.K2 20.95,29.84 22.23,31.11 25.27,31.11 v25.91,31.75 | v59.69,11.68 61.47,13.46 67.06,13.46 67.94,14.35 E5.6 | v26.42,44.83 27.56,45.97 33.66,45.97 34.16,46.48 43.69,46.48 v45.85,48.64 | v49.4,54.1 50.42,55.12 67.06,55.12 67.94,54.23 E14.6
K2  (via drill 0.61)
  Top 0.254: E14.1 55.63,52.07 54.74,51.18 54.74,42.8 55.63,41.91 E11.1 56.52,39.75 57.4,38.86 59.82,38.86 59.82,32.64 63.25,29.21 E8.4 | v60.58,5.33 60.58,3.94 60.71,3.81 E2.3 | v54.99,8.26 54.1,9.14 v54.1,22.61 | v21.59,31.88 21.46,32 21.46,49.15 v20.7,49.91 | v46.1,51.44 v48.13,53.47
  Bottom 0.254: U$1.K2 14.48,29.97 17.14,29.97 U$4.K1 18.41,31.11 19.18,31.88 v21.59,31.88 | 54.1,25.65 61.47,25.65 62.87,27.05 E8.4 | 54.1,25.65 45.72,25.65 43.81,23.75 E4.8 | v60.58,5.33 58.17,7.75 55.5,7.75 v54.99,8.26 | 54.1,25.65 v54.1,22.61 | v20.7,49.91 22.23,51.44 v46.1,51.44 | v48.13,53.47 48.39,53.21 55.24,53.21 E14.1
L1  (via drill 0.61)
  Top 0.254: v15.37,32.38 14.48,32.38 U$1.L1 | v67.31,11.68 67.31,4.83 66.29,3.81 E2.5 | v62.36,12.57 v62.36,20.19 62.36,23.75 59.05,27.05 E8.2 | v74.93,15.75 74.93,43.43 71.37,46.99 E11.8 | v43.31,30.1 44.58,28.83 v44.58,20.32
  Bottom 0.254: v15.37,32.38 19.68,32.38 U$4.L2 20.95,32.89 26.04,32.89 28.07,30.86 38.61,30.86 38.86,31.11 42.29,31.11 v43.31,30.1 | 76.33,14.35 75.44,13.46 69.09,13.46 v67.31,11.68 66.93,11.94 62.99,11.94 v62.36,12.57 | 76.33,14.35 83.19,14.35 E6.1 | 76.33,14.35 v74.93,15.75 | v44.58,20.32 44.7,20.19 v62.36,20.19
L2  (via drill 0.61)
  Top 0.254: E11.2 58.17,41.91 57.28,42.8 v57.28,45.47 57.28,50.8 58.17,51.69 58.17,52.07 E14.2 | E2.4 63.75,3.81 64.77,4.83 64.77,20.57 65.79,21.59 E5.10 | v63.5,37.85 64.9,36.45 64.9,33.91 65.79,33.02 65.79,29.21 E8.5 | v22.48,36.45 v22.48,41.91
  Bottom 0.254: U$1.L2 14.48,33.66 17.14,33.66 U$4.L1 18.41,34.42 21.08,34.42 22.48,35.81 v22.48,36.45 | E8.5 65.79,26.67 65.79,26.16 65.41,25.78 65.41,24.13 65.79,24.13 E5.10 | v63.5,37.85 60.96,37.85 59.05,39.75 E11.2 | v22.48,41.91 24.51,43.94 32.38,43.94 34.42,45.97 45.21,45.97 45.72,45.47 v57.28,45.47
M1  (via drill 0.61)
  Top 0.254: v15.37,35.43 14.48,35.43 U$1.M1 | E15.12 88.65,59.69 85.22,56.26 85.22,50.42 86.11,49.53 E12.13 86.11,46.99 85.22,46.1 v85.22,20.07 85.22,17.4 86.11,16.51 E6.2 | v72.64,9.91 72.52,9.78 72.52,7.49 68.83,3.81 E2.6 | v62.36,25.27 62.36,28.83 59.31,31.88 59.31,33.66 58.67,34.29 E8.13
  Bottom 0.254: E8.13 57.78,36.45 56.77,37.47 50.8,37.47 50.67,37.34 22.1,37.34 20.95,36.2 U$4.M2 19.68,35.43 v15.37,35.43 | v72.64,9.91 76.2,13.46 84.84,13.46 85.72,14.35 E6.2 | v62.36,25.27 62.36,21.08 72.64,21.08 73.66,20.07 v85.22,20.07
M2  (via drill 0.61)
  Top 0.254: v62.99,45.47 v62.99,43.43 62.99,42.16 63.25,41.91 E11.4 | v61.21,45.47 59.82,46.86 59.82,49.91 60.71,50.8 60.71,52.07 E14.3 60.71,54.61 v60.71,56.64 | E2.9 68.83,11.43 69.47,12.06 69.47,13.84 69.72,14.1 69.72,20.7 68.83,21.59 E5.9 68.33,24.13 68.33,26.67 E8.6 68.83,29.21 69.72,30.1 69.72,42.04 v68.33,43.43 | v16.26,40.89 16.26,38.35 17.14,37.47 U$4.M1 | v22.73,46.23 24.51,48.01 v24.51,54.36
  Bottom 0.254: U$4.M1 17.14,36.32 14.48,36.32 U$1.M2 | v61.21,45.47 v62.99,45.47 | v62.99,43.43 v68.33,43.43 | v16.26,40.89 16.26,42.04 18.54,42.04 v22.73,46.23 | v24.51,54.36 25.91,55.75 44.58,55.75 45.21,56.39 60.45,56.39 v60.71,56.64
N1  (via drill 0.61)
  Top 0.254: E15.11 91.19,59.69 90.3,58.8 90.3,50.67 89.15,49.53 E12.12 88.65,46.99 88.01,46.35 88.01,42.04 87.76,41.78 87.76,32.77 | v86.23,12.32 85.22,11.3 85.22,4.95 84.07,3.81 E3.1 | 87.76,32.77 87.76,17.4 88.65,16.51 E6.3 | v15.37,38.73 14.48,38.73 U$1.N1 | v87.63,32.77 87.76,32.77 | v63.12,32.77 62.23,31.88 61.34,31.88 61.34,32 60.96,32.38 60.96,34.29 E8.12
  Bottom 0.254: v86.23,12.32 88.27,14.35 E6.3 | E8.12 60.33,36.45 57.91,38.86 43.94,38.86 43.43,38.35 21.34,38.35 20.95,38.73 U$4.N2 19.68,38.73 v15.37,38.73 | v63.12,32.77 v87.63,32.77
N2  (via drill 0.61)
  Top 0.254: E2.8 70.74,11.3 69.98,12.06 69.98,12.57 70.87,13.46 72.26,13.46 72.26,19.68 71.37,20.57 71.37,21.59 E5.8 | E14.4 63.75,52.07 64.9,50.93 64.9,42.8 65.79,41.91 E11.5 | v66.29,25.4 64.64,27.05 64.64,33.4 63.75,34.29 E8.11 | v42.67,43.05 44.58,44.96 44.58,48.64 v47.37,51.44
  Bottom 0.254: U$1.N2 14.48,40.01 17.14,40.01 U$4.N1 18.41,40.51 23.24,40.51 24.89,38.86 41.15,38.86 42.04,39.75 42.04,43.05 v42.67,43.05 | E8.11 63.75,36.83 66.29,39.37 E11.5 | v66.29,25.4 68.83,25.4 70.48,23.75 E5.8 | v47.37,51.44 47.75,51.05 61.47,51.05 62.87,52.45 E14.4
P1  (via drill 0.61)
  Top 0.254: U$4.P2 19.68,41.78 14.48,41.78 U$1.P1 | E12.10 93.73,49.53 93.73,52.07 E15.5 | v86.74,5.84 86.74,3.94 86.61,3.81 E3.2 | v88.52,7.37 90.3,9.14 90.3,13.08 91.19,13.97 E6.4 | v83.69,8 82.68,9.02 82.68,25.78 83.57,26.67 E9.1 | v81.92,51.69 81.92,38.99 80.64,37.72 v80.64,30.99 v80.64,28.7 | v24.38,40.64 24.64,40.39 v24.64,36.45 | v51.18,34.42 52.96,32.64 v52.96,31.62
  Bottom 0.254: v88.52,7.37 88.27,7.37 v86.74,5.84 86.36,6.1 85.6,6.1 v83.69,8 | v81.92,51.69 82.04,51.56 87.5,51.56 87.5,54.23 88.39,55.12 92.46,55.12 93.34,54.23 E15.5 | v80.64,28.7 83.19,28.7 E9.1 | v24.38,40.64 24,41.02 21.21,41.02 20.95,41.27 U$4.P2 | v24.64,36.45 27.3,33.78 43.69,33.78 45.34,35.43 46.1,35.43 47.12,34.42 v51.18,34.42 | v52.96,31.62 53.59,30.99 v80.64,30.99
P2  (via drill 0.61)
  Top 0.254: E3.3 88.65,3.81 87.63,4.83 87.63,16.76 86.61,17.78 86.61,21.59 E6.13 | 69.98,50.04 69.98,44.07 72.64,41.4 v72.64,40.64 72.52,40.26 72.52,28.32 v72.9,27.94 | 69.98,50.04 69.98,54.48 70.23,54.74 70.23,59.05 70.87,59.69 E14.8 | v72.64,48.26 72.26,48.64 72.26,49.4 71.63,50.04 69.98,50.04
  Bottom 0.254: U$1.P2 14.48,42.55 17.14,42.55 U$4.P1 18.41,43.81 18.41,45.85 18.54,45.85 19.81,47.12 24.51,47.12 27.43,50.04 71.63,50.04 72.64,49.02 v72.64,48.26 | 68.39,38.92 68.83,39.37 E11.6 | 68.39,38.92 66.29,36.83 E8.10 | v72.64,40.64 72.64,38.86 68.45,38.86 68.39,38.92 | v72.9,27.94 75.18,25.65 83.82,25.65 85.72,23.75 E6.13
R1  (via drill 0.61)  (1 unrouted)
  Top 0.254: U$4.R2 19.68,45.09 14.48,45.09 U$1.R1 | E15.6 96.27,52.07 96.27,49.53 E12.9 96.27,46.99 95.12,45.85 95.12,33.91 92.58,31.37 92.58,26.8 91.44,25.65 v91.06,25.53 92.84,23.75 92.84,19.94 93.73,19.05 93.73,16.51 E6.5 93.73,13.97 93.73,13.46 92.84,12.57 92.84,4.7 93.73,3.81 E3.5
  Bottom 0.254: v91.06,25.53 88.52,25.53 87,27.05 E9.2
R2  (via drill 0.61)
  Top 0.254: E15.1 83.57,52.07 82.68,51.18 82.68,42.8 83.57,41.91 E12.1 83.57,39.37 82.68,38.48 82.68,28.83 v81.66,27.81 81.92,27.43 81.92,8.51 v82.04,8.38 | v89.66,5.33 91.19,3.81 E3.4 | v71.5,55.75 72.52,55.75 72.52,53.72 v72.64,53.59
  Bottom 0.254: U$1.R2 14.48,46.35 17.14,46.35 U$4.R1 18.41,47.62 19.18,48.39 19.18,53.47 25.78,53.47 27.56,55.24 44.83,55.24 45.34,55.75 v71.5,55.75 | E8.9 69.22,36.45 71.12,38.35 81.79,38.35 83.19,39.75 E12.1 | v81.66,27.81 83.31,26.16 85.85,26.16 88.27,23.75 E6.12 | v89.66,5.33 89.28,4.95 85.47,4.95 v82.04,8.38 | v72.64,53.59 72.77,53.47 83.19,53.47 E15.1
S1  (via drill 0.61)
  Top 0.254: U$4.S2 19.68,48.13 14.48,48.13 U$1.S1 | E3.6 96.27,3.81 95.76,4.32 95.76,8.64 95.38,9.02 95.38,13.08 96.27,13.97 E6.6 96.27,16.51 95.38,17.4 95.38,32.38 v95.25,32.77 96.01,32.77 97.92,34.67 97.92,42.29 98.81,43.18 98.81,46.99 E12.8 | v71.88,50.93 v73.66,49.15
  Bottom 0.254: v95.25,32.77 88.9,32.77 87,34.67 E9.13 | v71.88,50.93 71.5,50.55 22.61,50.55 20.95,48.9 U$4.S2 | v73.66,49.15 74.04,48.77 82.04,48.77 83.31,50.04 97.54,50.04 98.42,49.15 E12.8
S2  (via drill 0.61)
  Top 0.254: v92.71,13.72 92.58,13.84 92.58,19.43 91.69,20.32 91.69,21.59 E6.11 | E15.2 86.61,52.07 87.5,51.18 87.5,42.8 86.61,41.91 E12.2 | v81.03,12.57 79.76,13.84 v79.76,35.31 | v21.84,54.36 21.84,50.93 19.18,50.93 18.41,50.16 U$4.S1
  Bottom 0.254: U$4.S1 17.14,48.9 14.48,48.9 U$1.S2 | v92.71,13.72 92.46,13.46 89.41,13.46 87,11.05 E3.13 85.72,11.05 84.2,12.57 v81.03,12.57 | 79.76,36.96 82.93,36.96 85.72,39.75 E12.2 | 79.76,36.96 72.26,36.96 71.75,36.45 E8.8 | 79.76,36.96 v79.76,35.31 | v21.84,54.36 25.02,57.53 50.29,57.53 50.93,56.9 59.69,56.9 60.33,57.53 82.42,57.53 85.72,54.23 E15.2
T2  (via drill 0.61)
  Top 0.254: v92.58,51.69 92.58,42.8 91.69,41.91 E12.4 91.69,39.37 92.58,38.48 92.58,32.51 v91.19,31.11 | E3.12 89.15,11.43 89.79,12.06 89.79,13.84 90.04,14.1 v90.04,24.64 90.04,25.78 89.15,26.67 E9.3 89.15,29.21 89.15,30.48 v89.41,30.73 | v20.19,58.67 19.94,58.67 19.18,57.91 19.18,54.74 18.41,53.98 U$4.T1
  Bottom 0.254: U$4.T1 17.14,52.7 14.48,52.7 U$1.T2 | E15.3 89.53,52.45 90.42,51.56 92.46,51.56 v92.58,51.69 92.96,51.56 95.12,51.56 95.12,54.48 91.57,58.04 57.66,58.04 57.02,58.67 50.93,58.67 50.8,58.55 20.32,58.55 v20.19,58.67 | v90.04,24.64 92.46,24.64 93.34,23.75 E6.10 | v91.19,31.11 90.81,30.73 v89.41,30.73
U1  (via drill 0.61)
  Top 0.254: v15.37,54.48 14.48,54.48 U$1.U1 | v94.87,7.37 94.87,8.26 94.23,8.89 E3.10 | v96.9,32.38 103,26.29 v103,24.51 | v51.31,57.78 51.56,57.53 51.56,38.23 50.29,36.96 50.29,33.02 v50.67,32.64
  Bottom 0.254: v15.37,54.48 19.68,54.48 U$4.U2 20.95,55.24 23.75,58.04 51.05,58.04 v51.31,57.78 | v94.87,7.37 97.28,4.95 103.89,4.95 106.05,2.79 R4.2 107.31,2.29 108.58,2.29 R5.1 109.47,3.17 110.36,3.17 110.36,17.14 v103,24.51 | E9.12 89.53,34.67 90.55,33.66 95.63,33.66 v96.9,32.38 96.52,32.13 96.27,31.88 94.87,31.88 94.74,32 90.81,32 90.68,31.88 61.47,31.88 60.83,32.51 50.8,32.51 v50.67,32.64
U2  (via drill 0.61)  (1 unrouted)
  Top 0.254: E3.9 96.77,11.43 97.66,12.32 97.66,20.7 96.77,21.59 E6.9 | E9.4 91.19,29.21 90.3,30.1 90.3,36.96 v90.17,37.08 90.3,37.47 90.3,49.4 90.81,49.91 90.81,51.69 91.19,52.07 E15.4
  Bottom 0.254: U$4.U1 17.14,55.37 14.48,55.37 U$1.U2 | E9.4 92.08,27.05 95.38,23.75 95.89,23.75 E6.9 | v90.17,37.08 90.68,37.08 93.34,39.75 E12.5
V1  (via drill 0.61)  (1 unrouted)
  Top 0.254: v104.01,20.57 106.43,22.99 106.43,27.3 R7.2 | v15.37,57.15 14.48,57.15 14.48,57.28 U$1.V1
  Bottom 0.254: v104.01,20.57 107.31,17.27 107.82,17.27 107.82,12.32 107.06,11.56 106.3,11.56 105.92,11.94 92.96,11.94 92.08,11.05 E3.11 | E9.6 97.16,27.05 98.04,26.16 104.52,26.16 106.05,27.69 R7.2 107.31,27.69 108.58,27.69 R6.1 | v15.37,57.15 19.68,57.15 U$4.V2
V2  (via drill 0.61)  (1 unrouted)
  Top 0.254: E3.8 99.31,11.43 100.2,12.32 100.2,20.7 99.31,21.59 E6.8 | v94.49,30.73 94.23,30.48 94.23,29.21 E9.5 | E15.8 98.81,59.69 97.66,58.55 97.66,42.8 96.77,41.91 E12.6
  Bottom 0.254: U$4.V1 17.14,58.04 14.48,58.04 U$1.V2 | E9.5 94.61,27.05 97.92,23.75 98.42,23.75 E6.8 | v94.49,30.73 97.79,30.73 97.79,36.58 97.03,37.34 96.77,37.34 96.77,39.37 E12.6
VCC  (via drill 0.61)
  Top 0.381: C7.1 46.23,34.67 47.12,35.56 v47.12,35.69 46.86,36.07 46.86,45.47 45.97,46.35 C10.1 | E10.14 28.19,46.99 29.08,46.1 29.08,37.72 28.19,36.83 E7.14 27.69,34.29 27.05,33.66 27.05,29.34 26.8,29.08 26.8,25.02 27.69,24.13 E4.14 | E5.14 55.63,21.59 54.74,20.7 54.74,12.32 55.63,11.43 E2.14
  Bottom 0.381: v47.12,35.69 47.24,35.56 55.24,35.56 E8.14 56.52,34.67 57.4,33.78 73.28,33.78 C8.1 74.3,34.29 83.57,34.29 E9.14 | C10.1 46.35,46.99 55.63,46.99 E11.14 56.52,47.37 57.4,46.48 73.28,46.48 C11.1 74.3,47.24 74.42,47.37 83.19,47.37 E12.14 84.45,47.37 85.34,46.48 101.22,46.48 C12.1 | E13.14 28.57,60.07 29.34,59.31 29.84,59.31 29.97,59.18 44.58,59.18 44.83,59.44 45.09,59.44 C13.1 46.35,59.69 55.63,59.69 E14.14 56.52,60.07 57.4,59.18 73.28,59.18 C14.1 74.3,59.94 74.42,60.07 83.19,60.07 E15.14 84.45,60.07 85.34,59.18 101.22,59.18 C15.1 101.85,59.05 101.85,55.75 102.11,55.75 102.74,55.12 102.74,47.62 101.85,47.62 C12.1 | C9.1 102.23,34.54 104.65,36.96 107.7,36.96 108.58,37.85 R6.2 | C12.1 101.85,46.35 109.47,38.73 R6.2 | E5.14 55.63,21.59 46.35,21.59 C4.1 45.09,21.34 44.2,21.34 43.94,21.08 29.46,21.08 28.57,21.97 E4.14 | C5.1 74.3,21.84 74.42,21.97 83.19,21.97 E6.14 84.45,21.97 85.34,21.08 101.22,21.08 C6.1 | C6.1 102.23,21.59 104.39,21.59 108.97,17.02 108.97,13.34 R5.2 108.71,12.32 107.31,10.92 104.01,10.92 102.23,9.14 C3.1 101.22,8.38 85.34,8.38 84.45,9.27 E3.14 83.19,9.4 74.55,9.4 74.3,9.14 C2.1 73.03,8.64 72.77,8.38 57.4,8.38 56.52,9.27 E2.14 55.24,9.27 46.48,9.27 46.35,9.14 C1.1 45.09,8.64 44.83,8.38 28.19,8.38 28.07,8.38 | U$1.A2 14.61,4.45 17.14,4.45 U$4.A1 18.41,5.71 18.92,6.22 28.07,6.22 28.07,8.38 | 28.07,8.38 28.07,8.89 E1.14 | R6.2 109.47,37.47 109.47,29.08 109.73,29.08 110.36,28.45 110.36,25.53 102.62,25.53 101.85,24.77 101.85,22.23 C6.1

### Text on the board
tNames: M119 | Install Resistors Unless M111 or M115 | M117 | M115 | M113 | Fill Only One Column | M111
